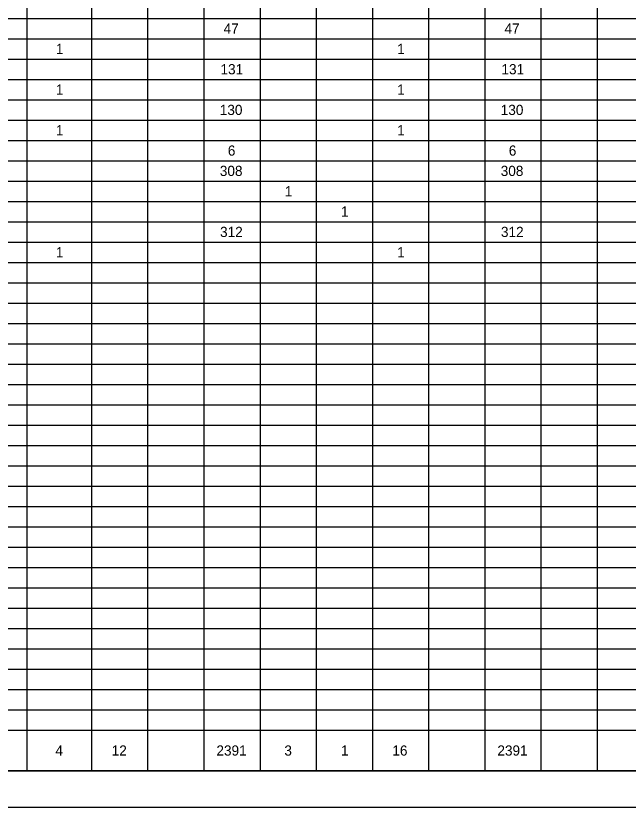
# Model space of a CAD drawing. Extents: x 0 to 34, y 0 to 22.
# Drawn here: x 17.13 to 25.56, y 0 to 10.89 of the extents above; entities that cross this region are included whole.
import ezdxf

# ---------------------------------------------------------------- set-up
doc = ezdxf.new("R2010")
doc.units = 0
for name, color, linetype in [('Default', 7, 'Continuous'), ('SH_Border', 7, 'Continuous'), ('SH_Cut_Line', 7, 'Continuous')]:
    doc.layers.add(name, color=color, linetype=linetype)

msp = doc.modelspace()

# ---------------------------------------------------------------- linework, layer by layer
at = {"layer": 'Default'}
for p, q in [((17.279, 21.5), (17.279, 0.5)), ((18.168, 21.5), (18.168, 0.5)), ((18.942, 21.5), (18.942, 0.5)), ((19.716, 21.5), (19.716, 0.5)), ((20.491, 21.5), (20.491, 0.5)), ((21.265, 21.5), (21.265, 0.5)), ((22.039, 21.5), (22.039, 0.5)), ((22.813, 21.5), (22.813, 0.5)), ((23.587, 21.5), (23.587, 0.5)), ((24.361, 21.5), (24.361, 0.5)), ((25.135, 21.5), (25.135, 0.5)), ((1.5, 10.86), (31.724, 10.86)), ((1.5, 10.58), (31.724, 10.58)), ((1.5, 10.3), (31.724, 10.3)), ((1.5, 10.02), (31.724, 10.02)), ((1.5, 9.74), (31.724, 9.74)), ((1.5, 9.46), (31.724, 9.46)), ((1.5, 9.18), (31.724, 9.18)), ((1.5, 8.9), (31.724, 8.9)), ((1.5, 8.62), (31.724, 8.62)), ((1.5, 8.34), (31.724, 8.34)), ((1.5, 8.06), (31.724, 8.06)), ((1.5, 7.78), (31.724, 7.78)), ((1.5, 7.5), (31.724, 7.5)), ((1.5, 7.22), (31.724, 7.22)), ((1.5, 6.94), (31.724, 6.94)), ((1.5, 6.66), (31.724, 6.66)), ((1.5, 6.38), (31.724, 6.38)), ((1.5, 6.1), (31.724, 6.1)), ((1.5, 5.82), (31.724, 5.82)), ((1.5, 5.54), (31.724, 5.54)), ((1.5, 5.26), (31.724, 5.26)), ((1.5, 4.98), (31.724, 4.98)), ((1.5, 4.7), (31.724, 4.7)), ((1.5, 4.42), (31.724, 4.42)), ((1.5, 4.14), (31.724, 4.14)), ((1.5, 3.86), (31.724, 3.86)), ((1.5, 3.58), (31.724, 3.58)), ((1.5, 3.3), (31.724, 3.3)), ((1.5, 3.02), (31.724, 3.02)), ((1.5, 2.74), (31.724, 2.74)), ((1.5, 2.46), (31.724, 2.46)), ((1.5, 2.18), (31.724, 2.18)), ((1.5, 1.9), (31.724, 1.9)), ((1.5, 1.62), (31.724, 1.62)), ((1.5, 1.34), (31.724, 1.34)), ((1.5, 1.06), (31.724, 1.06)), ((1.5, 0.5), (31.724, 0.5))]:
    msp.add_line(p, q, dxfattribs=at)
at = {"layer": 'SH_Border'}
msp.add_lwpolyline([(1.5, 21.5), (33.5, 21.5), (33.5, 0.5), (1.5, 0.5)], close=True, dxfattribs=at)
at = {"layer": 'SH_Cut_Line'}
msp.add_lwpolyline([(0, 0), (34, 0), (34, 22), (0, 22)], close=True, dxfattribs=at)

# ---------------------------------------------------------------- texts
at = {"layer": 'Default'}
for s, p in [('47', (19.989, 10.65)), ('47', (23.859, 10.65)), ('1', (17.678, 10.37)), ('1', (22.38, 10.37)), ('131', (19.946, 10.09)), ('131', (23.817, 10.09)), ('1', (17.678, 9.81)), ('1', (22.38, 9.81)), ('130', (19.936, 9.53)), ('130', (23.807, 9.53)), ('1', (17.678, 9.25)), ('1', (22.38, 9.25)), ('6', (20.047, 8.97)), ('6', (23.918, 8.97)), ('308', (19.937, 8.69)), ('308', (23.807, 8.69)), ('1', (20.832, 8.41)), ('1', (21.606, 8.13)), ('312', (19.94, 7.85)), ('312', (23.81, 7.85)), ('1', (17.678, 7.57)), ('1', (22.38, 7.57)), ('4', (17.672, 0.71)), ('12', (18.447, 0.71)), ('2391', (19.89, 0.71)), ('3', (20.826, 0.71)), ('1', (21.606, 0.71)), ('16', (22.314, 0.71)), ('2391', (23.761, 0.71))]:
    msp.add_text(s, height=0.14, dxfattribs=at).set_placement(p)

doc.saveas('drawing.dxf')
